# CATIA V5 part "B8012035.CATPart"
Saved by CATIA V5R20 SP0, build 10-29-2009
Part number: B8012035
Revision: 12
Definition: design
Nomenclature: B8012035
Source: made
Description: NOT SPECIFIED
Bounding box of the stored display mesh (mm): x -18 to 18, y -18 to 18, z 0 to 35
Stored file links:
  C:\Users\Utente\Desktop\3D files B801\B8012035.CATPart
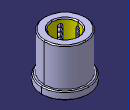
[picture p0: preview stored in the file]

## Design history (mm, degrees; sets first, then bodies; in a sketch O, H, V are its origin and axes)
Body1 "MANIFOLD_SOLID_BREP #38" (main body)
  Solid1: solid without history
Body2 "MANIFOLD_SOLID_BREP #76"
  Solid2: solid without history
Body3 "MANIFOLD_SOLID_BREP #114"
  Solid3: solid without history
Body4 "MANIFOLD_SOLID_BREP #152"
  Solid4: solid without history
Body5 "MANIFOLD_SOLID_BREP #190"
  Solid5: solid without history
Body6 "MANIFOLD_SOLID_BREP #228"
  Solid6: solid without history
Body7 "MANIFOLD_SOLID_BREP #266"
  Solid7: solid without history
Body8 "MANIFOLD_SOLID_BREP #304"
  Solid8: solid without history
Body9 "MANIFOLD_SOLID_BREP #342"
  Solid9: solid without history
Body10 "MANIFOLD_SOLID_BREP #1864"
  Solid10: solid without history
Body11 "MANIFOLD_SOLID_BREP #1902"
  Solid11: solid without history
Body12 "MANIFOLD_SOLID_BREP #1940"
  Solid12: solid without history
Body13 "MANIFOLD_SOLID_BREP #1978"
  Solid13: solid without history
Body14 "MANIFOLD_SOLID_BREP #2016"
  Solid14: solid without history
Body15 "MANIFOLD_SOLID_BREP #2054"
  Solid15: solid without history
Body16 "MANIFOLD_SOLID_BREP #2092"
  Solid16: solid without history
Body17 "MANIFOLD_SOLID_BREP #2130"
  Solid17: solid without history
Body18 "MANIFOLD_SOLID_BREP #2168"
  Solid18: solid without history
Body19 "MANIFOLD_SOLID_BREP #2206"
  Solid19: solid without history
Body20 "MANIFOLD_SOLID_BREP #2244"
  Solid20: solid without history
Body21 "MANIFOLD_SOLID_BREP #2282"
  Solid21: solid without history
Body22 "MANIFOLD_SOLID_BREP #2320"
  Solid22: solid without history
Body23 "MANIFOLD_SOLID_BREP #2358"
  Solid23: solid without history
Body24 "MANIFOLD_SOLID_BREP #2396"
  Solid24: solid without history
Body25 "MANIFOLD_SOLID_BREP #2434"
  Solid25: solid without history
Body26 "MANIFOLD_SOLID_BREP #2472"
  Solid26: solid without history
Body27 "MANIFOLD_SOLID_BREP #2510"
  Solid27: solid without history
Body28 "MANIFOLD_SOLID_BREP #2548"
  Solid28: solid without history
Body29 "MANIFOLD_SOLID_BREP #2586"
  Solid29: solid without history
Body30 "MANIFOLD_SOLID_BREP #2624"
  Solid30: solid without history
Body31 "MANIFOLD_SOLID_BREP #2662"
  Solid31: solid without history
Body32 "MANIFOLD_SOLID_BREP #2700"
  Solid32: solid without history
Body33 "MANIFOLD_SOLID_BREP #2738"
  Solid33: solid without history
Body34 "MANIFOLD_SOLID_BREP #2776"
  Solid34: solid without history
Body35 "MANIFOLD_SOLID_BREP #2814"
  Solid35: solid without history
Body36 "MANIFOLD_SOLID_BREP #2852"
  Solid36: solid without history
Body37 "MANIFOLD_SOLID_BREP #2890"
  Solid37: solid without history
Body38 "MANIFOLD_SOLID_BREP #2928"
  Solid38: solid without history
Body39 "MANIFOLD_SOLID_BREP #2966"
  Solid39: solid without history
Body40 "MANIFOLD_SOLID_BREP #3004"
  Solid40: solid without history
Body41 "MANIFOLD_SOLID_BREP #3042"
  Solid41: solid without history
Body42 "MANIFOLD_SOLID_BREP #3080"
  Solid42: solid without history
Body43 "MANIFOLD_SOLID_BREP #3118"
  Solid43: solid without history
Body44 "MANIFOLD_SOLID_BREP #3156"
  Solid44: solid without history
Body45 "MANIFOLD_SOLID_BREP #3194"
  Solid45: solid without history
Body46 "MANIFOLD_SOLID_BREP #3232"
  Solid46: solid without history
Body47 "MANIFOLD_SOLID_BREP #3270"
  Solid47: solid without history
Body48 "MANIFOLD_SOLID_BREP #3308"
  Solid48: solid without history
Body49 "MANIFOLD_SOLID_BREP #3346"
  Solid49: solid without history
Body50 "MANIFOLD_SOLID_BREP #3384"
  Solid50: solid without history
Body51 "MANIFOLD_SOLID_BREP #3422"
  Solid51: solid without history
Body52 "MANIFOLD_SOLID_BREP #3460"
  Solid52: solid without history
Body53 "MANIFOLD_SOLID_BREP #3498"
  Solid53: solid without history
Body54 "MANIFOLD_SOLID_BREP #3536"
  Solid54: solid without history
Body55 "MANIFOLD_SOLID_BREP #3574"
  Solid55: solid without history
